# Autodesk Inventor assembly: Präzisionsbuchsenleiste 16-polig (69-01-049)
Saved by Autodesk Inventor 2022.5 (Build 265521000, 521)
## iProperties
Created: 2024-12
Part Number: Präzisionsbuchsenleiste 16-polig (69-01-049)
Document SubType Name: Assembly
Designer: AdminForWorker
Title: Präzisionsbuchsenleiste 16-polig (69-01-049)
Author: AdminForWorker
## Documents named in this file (3)
- c:\worker\convert-fusion-r05-cosv3\tmp\job-1\137\temp\files\71a56e1c-7209-48b3-b2cf-f79746e6226c\Präzisionsbuchsenleiste 16-polig (69-01-049).iam
- c:\worker\convert-fusion-r05-cosv3\tmp\job-1\137\temp\files\71a56e1c-7209-48b3-b2cf-f79746e6226c\Präzisionsbuchsenleiste 16 (P2SSW-108-01-G-D)_Gehäuse.ipt
- c:\worker\convert-fusion-r05-cosv3\tmp\job-1\137\temp\files\71a56e1c-7209-48b3-b2cf-f79746e6226c\Präzisionssbuchsenleiste 16 (P2SSW-108-01-G-D)_Pins.ipt
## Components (2 placed, 2 different names)
1. Präzisionsbuchsenleiste 16 (P2SSW-108-01-G-D)_Gehäuse:1
2. Präzisionssbuchsenleiste 16 (P2SSW-108-01-G-D)_Pins:1
